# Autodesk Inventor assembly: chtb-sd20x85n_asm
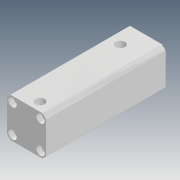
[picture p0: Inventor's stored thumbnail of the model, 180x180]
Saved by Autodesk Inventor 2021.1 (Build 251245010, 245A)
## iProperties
Company: Microsoft
Created: 2018-04
Part Number: chtb-sd20x85n_asm
Description: STEP AP214
Document SubType Name: Assembly
Designer: user
Title: chtb-sd20x85n_asm.STEP
Author: Windows
Revision Number: ÈÎºÎ
Sending System: SolidWorks 2015
Preprocessor: SwSTEP 2.0
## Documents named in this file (4)
- D:\Vault_2016\Projekty\Clamptek\Hydraulic\CHTB\CHTB-20\Inventor\CHTB-SD20x85N\chtb-sd20x85n_asm.iam
- D:\Vault_2016\Projekty\Clamptek\Hydraulic\CHTB\CHTB-20\Inventor\CHTB-SD20x85N\CHTB-SD20X85NBT.ipt
- D:\Vault_2016\Projekty\Clamptek\Hydraulic\CHTB\CHTB-20\Inventor\CHTB-SD20x85N\CHTB-SD20X85NHSG.ipt
- D:\Vault_2016\Projekty\Clamptek\Hydraulic\CHTB\CHTB-20\Inventor\CHTB-SD20x85N\QG.ipt
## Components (3 placed, 3 different names)
1. CHTB-SD20X85NBT_1
2. CHTB-SD20X85NHSG_2
3. QG_3
